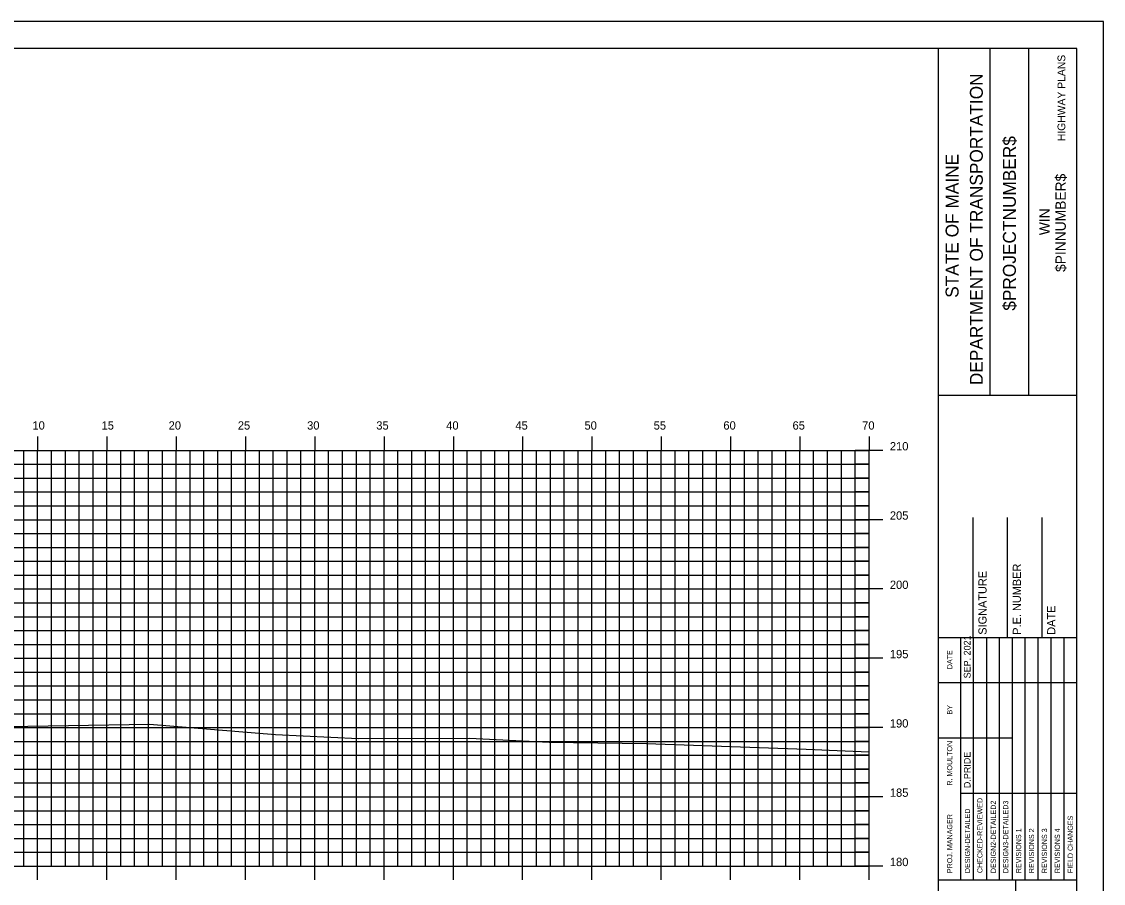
# Model space of a CAD drawing. Extents: x 1723321 to 1723493, y 458501 to 458611.
# Drawn here: x 1723412.9 to 1723490.9, y 458549 to 458611.2 of the extents above; entities that cross this region are included whole.
import ezdxf

# ---------------------------------------------------------------- set-up
doc = ezdxf.new("R2010")
doc.units = 0
for name, color, linetype in [('BORDER', 7, 'Continuous'), ('H_V ANNOTATION', 7, 'Continuous'), ('HIGHWAY_TITLE', 7, 'Continuous'), ('MAJOR', 7, 'Continuous'), ('MINOR', 7, 'Continuous'), ('PLOT BOUNDARY', 7, 'Continuous'), ('S_Roadway_Centerline', 7, 'Continuous')]:
    doc.layers.add(name, color=color, linetype=linetype)

msp = doc.modelspace()

# ---------------------------------------------------------------- linework, layer by layer
at = {"layer": 'BORDER'}
for p, q in [((1723479.029, 458504.254), (1723479.029, 458609.254)), ((1723482.758, 458584.251), (1723482.758, 458609.251)), ((1723485.553, 458584.251), (1723485.553, 458609.251)), ((1723479.03, 458584.248), (1723489.029, 458584.248)), ((1723481.529, 458566.757), (1723481.529, 458575.405)), ((1723484.029, 458566.757), (1723484.029, 458575.405)), ((1723486.529, 458566.757), (1723486.529, 458575.405)), ((1723479.029, 458566.757), (1723489.029, 458566.757)), ((1723479.029, 458549.257), (1723489.029, 458549.257)), ((1723484.62, 458514.257), (1723484.62, 458549.257))]:
    msp.add_line(p, q, dxfattribs=at)
msp.add_lwpolyline([(1723329.029, 458504.254), (1723489.029, 458504.254), (1723489.029, 458609.254), (1723329.029, 458609.254)], close=True, dxfattribs=at)
for points in [[(1723480.644, 458563.507), (1723480.644, 458566.757)], [(1723481.576, 458549.26), (1723481.576, 458566.757)], [(1723482.508, 458566.757), (1723482.508, 458549.26)], [(1723483.44, 458549.26), (1723483.44, 458566.757)], [(1723484.372, 458549.26), (1723484.372, 458566.757)], [(1723485.303, 458549.26), (1723485.303, 458566.757)], [(1723486.235, 458549.26), (1723486.235, 458566.757)], [(1723487.167, 458549.26), (1723487.167, 458566.757)], [(1723488.098, 458549.26), (1723488.098, 458566.757)], [(1723480.645, 458549.26), (1723480.645, 458566.051)], [(1723479.029, 458563.507), (1723489.029, 458563.507)], [(1723479.029, 458559.507), (1723480.645, 458559.507)], [(1723480.644, 458559.507), (1723484.371, 458559.507)], [(1723480.644, 458555.507), (1723489.029, 458555.507)]]:
    msp.add_lwpolyline(points, dxfattribs=at)
at = {"layer": 'MAJOR'}
for p, q in [((1723414.029, 458581.256), (1723414.029, 458580.254)), ((1723419.029, 458581.256), (1723419.029, 458580.254)), ((1723424.029, 458581.256), (1723424.029, 458580.254)), ((1723429.029, 458581.256), (1723429.029, 458580.254)), ((1723434.029, 458581.256), (1723434.029, 458580.254)), ((1723439.029, 458581.256), (1723439.029, 458580.254)), ((1723444.029, 458581.256), (1723444.029, 458580.254)), ((1723449.029, 458581.256), (1723449.029, 458580.254)), ((1723454.029, 458581.256), (1723454.029, 458580.254)), ((1723459.029, 458581.256), (1723459.029, 458580.254)), ((1723464.029, 458581.256), (1723464.029, 458580.254)), ((1723469.029, 458581.256), (1723469.029, 458580.254)), ((1723474.029, 458581.256), (1723474.029, 458580.254)), ((1723334.029, 458580.254), (1723474.029, 458580.254)), ((1723334.029, 458580.254), (1723474.029, 458580.254)), ((1723414.029, 458550.254), (1723414.029, 458580.254)), ((1723419.029, 458550.254), (1723419.029, 458580.254)), ((1723424.029, 458550.254), (1723424.029, 458580.254)), ((1723429.029, 458550.254), (1723429.029, 458580.254)), ((1723434.029, 458550.254), (1723434.029, 458580.254)), ((1723439.029, 458550.254), (1723439.029, 458580.254)), ((1723444.029, 458550.254), (1723444.029, 458580.254)), ((1723449.029, 458550.254), (1723449.029, 458580.254)), ((1723454.029, 458550.254), (1723454.029, 458580.254)), ((1723459.029, 458550.254), (1723459.029, 458580.254)), ((1723464.029, 458550.254), (1723464.029, 458580.254)), ((1723469.029, 458550.254), (1723469.029, 458580.254)), ((1723475.031, 458580.254), (1723473.027, 458580.254)), ((1723474.029, 458550.254), (1723474.029, 458580.254)), ((1723474.029, 458550.254), (1723474.029, 458580.254)), ((1723334.029, 458575.254), (1723474.029, 458575.254)), ((1723475.031, 458575.254), (1723473.027, 458575.254)), ((1723334.029, 458570.254), (1723474.029, 458570.254)), ((1723475.031, 458570.254), (1723473.027, 458570.254)), ((1723334.029, 458565.254), (1723474.029, 458565.254)), ((1723475.031, 458565.254), (1723473.027, 458565.254)), ((1723334.029, 458560.254), (1723474.029, 458560.254)), ((1723475.031, 458560.254), (1723473.027, 458560.254)), ((1723334.029, 458555.254), (1723474.029, 458555.254)), ((1723475.031, 458555.254), (1723473.027, 458555.254)), ((1723334.029, 458550.254), (1723474.029, 458550.254)), ((1723334.029, 458550.254), (1723474.029, 458550.254)), ((1723414.029, 458549.252), (1723414.029, 458550.254)), ((1723419.029, 458549.252), (1723419.029, 458550.254)), ((1723424.029, 458549.252), (1723424.029, 458550.254)), ((1723429.029, 458549.252), (1723429.029, 458550.254)), ((1723434.029, 458549.252), (1723434.029, 458550.254)), ((1723439.029, 458549.252), (1723439.029, 458550.254)), ((1723444.029, 458549.252), (1723444.029, 458550.254)), ((1723449.029, 458549.252), (1723449.029, 458550.254)), ((1723454.029, 458549.252), (1723454.029, 458550.254)), ((1723459.029, 458549.252), (1723459.029, 458550.254)), ((1723464.029, 458549.252), (1723464.029, 458550.254)), ((1723469.029, 458549.252), (1723469.029, 458550.254)), ((1723475.031, 458550.254), (1723473.027, 458550.254)), ((1723474.029, 458549.252), (1723474.029, 458550.254))]:
    msp.add_line(p, q, dxfattribs=at)
at = {"layer": 'MINOR'}
for p, q in [((1723413.029, 458550.254), (1723413.029, 458580.254)), ((1723415.029, 458550.254), (1723415.029, 458580.254)), ((1723416.029, 458550.254), (1723416.029, 458580.254)), ((1723417.029, 458550.254), (1723417.029, 458580.254)), ((1723418.029, 458550.254), (1723418.029, 458580.254)), ((1723420.029, 458550.254), (1723420.029, 458580.254)), ((1723421.029, 458550.254), (1723421.029, 458580.254)), ((1723422.029, 458550.254), (1723422.029, 458580.254)), ((1723423.029, 458550.254), (1723423.029, 458580.254)), ((1723425.029, 458550.254), (1723425.029, 458580.254)), ((1723426.029, 458550.254), (1723426.029, 458580.254)), ((1723427.029, 458550.254), (1723427.029, 458580.254)), ((1723428.029, 458550.254), (1723428.029, 458580.254)), ((1723430.029, 458550.254), (1723430.029, 458580.254)), ((1723431.029, 458550.254), (1723431.029, 458580.254)), ((1723432.029, 458550.254), (1723432.029, 458580.254)), ((1723433.029, 458550.254), (1723433.029, 458580.254)), ((1723435.029, 458550.254), (1723435.029, 458580.254)), ((1723436.029, 458550.254), (1723436.029, 458580.254)), ((1723437.029, 458550.254), (1723437.029, 458580.254)), ((1723438.029, 458550.254), (1723438.029, 458580.254)), ((1723440.029, 458550.254), (1723440.029, 458580.254)), ((1723441.029, 458550.254), (1723441.029, 458580.254)), ((1723442.029, 458550.254), (1723442.029, 458580.254)), ((1723443.029, 458550.254), (1723443.029, 458580.254)), ((1723445.029, 458550.254), (1723445.029, 458580.254)), ((1723446.029, 458550.254), (1723446.029, 458580.254)), ((1723447.029, 458550.254), (1723447.029, 458580.254)), ((1723448.029, 458550.254), (1723448.029, 458580.254)), ((1723450.029, 458550.254), (1723450.029, 458580.254)), ((1723451.029, 458550.254), (1723451.029, 458580.254)), ((1723452.029, 458550.254), (1723452.029, 458580.254)), ((1723453.029, 458550.254), (1723453.029, 458580.254)), ((1723455.029, 458550.254), (1723455.029, 458580.254)), ((1723456.029, 458550.254), (1723456.029, 458580.254)), ((1723457.029, 458550.254), (1723457.029, 458580.254)), ((1723458.029, 458550.254), (1723458.029, 458580.254)), ((1723460.029, 458550.254), (1723460.029, 458580.254)), ((1723461.029, 458550.254), (1723461.029, 458580.254)), ((1723462.029, 458550.254), (1723462.029, 458580.254)), ((1723463.029, 458550.254), (1723463.029, 458580.254)), ((1723465.029, 458550.254), (1723465.029, 458580.254)), ((1723466.029, 458550.254), (1723466.029, 458580.254)), ((1723467.029, 458550.254), (1723467.029, 458580.254)), ((1723468.029, 458550.254), (1723468.029, 458580.254)), ((1723470.029, 458550.254), (1723470.029, 458580.254)), ((1723471.029, 458550.254), (1723471.029, 458580.254)), ((1723472.029, 458550.254), (1723472.029, 458580.254)), ((1723473.029, 458550.254), (1723473.029, 458580.254)), ((1723334.029, 458579.254), (1723474.029, 458579.254)), ((1723474.029, 458579.254), (1723473.027, 458579.254)), ((1723334.029, 458578.254), (1723474.029, 458578.254)), ((1723474.029, 458578.254), (1723473.027, 458578.254)), ((1723334.029, 458577.254), (1723474.029, 458577.254)), ((1723474.029, 458577.254), (1723473.027, 458577.254)), ((1723334.029, 458576.254), (1723474.029, 458576.254)), ((1723474.029, 458576.254), (1723473.027, 458576.254)), ((1723334.029, 458574.254), (1723474.029, 458574.254)), ((1723474.029, 458574.254), (1723473.027, 458574.254)), ((1723334.029, 458573.254), (1723474.029, 458573.254)), ((1723474.029, 458573.254), (1723473.027, 458573.254)), ((1723334.029, 458572.254), (1723474.029, 458572.254)), ((1723474.029, 458572.254), (1723473.027, 458572.254)), ((1723334.029, 458571.254), (1723474.029, 458571.254)), ((1723474.029, 458571.254), (1723473.027, 458571.254)), ((1723334.029, 458569.254), (1723474.029, 458569.254)), ((1723474.029, 458569.254), (1723473.027, 458569.254)), ((1723334.029, 458568.254), (1723474.029, 458568.254)), ((1723474.029, 458568.254), (1723473.027, 458568.254)), ((1723334.029, 458567.254), (1723474.029, 458567.254)), ((1723474.029, 458567.254), (1723473.027, 458567.254)), ((1723334.029, 458566.254), (1723474.029, 458566.254)), ((1723474.029, 458566.254), (1723473.027, 458566.254)), ((1723334.029, 458564.254), (1723474.029, 458564.254)), ((1723474.029, 458564.254), (1723473.027, 458564.254)), ((1723334.029, 458563.254), (1723474.029, 458563.254)), ((1723474.029, 458563.254), (1723473.027, 458563.254)), ((1723334.029, 458562.254), (1723474.029, 458562.254)), ((1723474.029, 458562.254), (1723473.027, 458562.254)), ((1723334.029, 458561.254), (1723474.029, 458561.254)), ((1723474.029, 458561.254), (1723473.027, 458561.254)), ((1723334.029, 458559.254), (1723474.029, 458559.254)), ((1723474.029, 458559.254), (1723473.027, 458559.254)), ((1723334.029, 458558.254), (1723474.029, 458558.254)), ((1723474.029, 458558.254), (1723473.027, 458558.254)), ((1723334.029, 458557.254), (1723474.029, 458557.254)), ((1723474.029, 458557.254), (1723473.027, 458557.254)), ((1723334.029, 458556.254), (1723474.029, 458556.254)), ((1723474.029, 458556.254), (1723473.027, 458556.254)), ((1723334.029, 458554.254), (1723474.029, 458554.254)), ((1723474.029, 458554.254), (1723473.027, 458554.254)), ((1723334.029, 458553.254), (1723474.029, 458553.254)), ((1723474.029, 458553.254), (1723473.027, 458553.254)), ((1723334.029, 458552.254), (1723474.029, 458552.254)), ((1723474.029, 458552.254), (1723473.027, 458552.254)), ((1723334.029, 458551.254), (1723474.029, 458551.254)), ((1723474.029, 458551.254), (1723473.027, 458551.254))]:
    msp.add_line(p, q, dxfattribs=at)
at = {"layer": 'PLOT BOUNDARY'}
msp.add_lwpolyline([(1723320.936, 458501.195), (1723490.936, 458501.195), (1723490.936, 458611.195), (1723320.936, 458611.195)], close=True, dxfattribs=at)
at = {"layer": 'S_Roadway_Centerline'}
msp.add_lwpolyline([(1723334.029, 458562.416), (1723335.834, 458562.354), (1723338.025, 458562.255), (1723349.598, 458561.79), (1723356.493, 458561.701), (1723361.621, 458561.642), (1723371.34, 458561.107), (1723375.346, 458560.975), (1723380.963, 458560.978), (1723398.602, 458560.98), (1723404.466, 458560.596), (1723411.856, 458560.327), (1723422.097, 458560.488), (1723431.206, 458559.748), (1723437.19, 458559.453), (1723445.206, 458559.48), (1723450.944, 458559.196), (1723457.969, 458559.095), (1723469.498, 458558.688), (1723470.086, 458558.662), (1723471.145, 458558.626), (1723474.029, 458558.512)], dxfattribs=at)

# ---------------------------------------------------------------- texts
at = {"layer": 'BORDER'}
for s, height, p in [('DEPARTMENT OF TRANSPORTATION', 0.93176, (1723482.236, 458584.96)), ('$PROJECTNUMBER$', 0.93176, (1723484.621, 458590.333)), ('STATE OF MAINE', 0.93176, (1723480.484, 458591.266)), ('$PINNUMBER$', 0.74527, (1723488.225, 458593.129)), ('WIN', 0.7453, (1723487.066, 458595.784)), ('P.E. NUMBER', 0.59055, (1723484.99, 458566.949)), ('SIGNATURE', 0.5906, (1723482.509, 458566.949)), ('DATE', 0.5906, (1723487.47, 458566.949)), ('SEP. 2021', 0.4845, (1723481.352, 458563.803)), ('DATE', 0.3714, (1723480.033, 458564.463)), ('BY', 0.3714, (1723480.033, 458561.192)), ('R. MOULTON', 0.3727, (1723480.033, 458556.06)), ('D.PRIDE', 0.4845, (1723481.352, 458555.88)), ('CHECKED-REVIEWED', 0.37275, (1723482.21, 458549.745)), ('DESIGN2-DETAILED2', 0.37275, (1723483.179, 458549.745)), ('DESIGN3-DETAILED3', 0.37275, (1723484.073, 458549.745)), ('DESIGN-DETAILED', 0.37275, (1723481.316, 458549.745)), ('PROJ. MANAGER', 0.37275, (1723480.033, 458549.745)), ('FIELD CHANGES', 0.37275, (1723488.732, 458549.745)), ('REVISIONS 1', 0.37275, (1723485.005, 458549.745)), ('REVISIONS 2', 0.37275, (1723485.937, 458549.745)), ('REVISIONS 3', 0.37275, (1723486.868, 458549.745)), ('REVISIONS 4', 0.37275, (1723487.8, 458549.745))]:
    msp.add_text(s, height=height, rotation=90, dxfattribs=at).set_placement(p)
at = {"layer": 'H_V ANNOTATION'}
for s, p in [('10', (1723413.654, 458581.754)), ('15', (1723418.646, 458581.754)), ('20', (1723423.483, 458581.754)), ('25', (1723428.475, 458581.754)), ('30', (1723433.477, 458581.754)), ('35', (1723438.469, 458581.754)), ('40', (1723443.515, 458581.754)), ('45', (1723448.507, 458581.754)), ('50', (1723453.493, 458581.754)), ('55', (1723458.485, 458581.754)), ('60', (1723463.515, 458581.754)), ('65', (1723468.507, 458581.754)), ('70', (1723473.531, 458581.754)), ('210', (1723475.529, 458580.254)), ('205', (1723475.529, 458575.254)), ('200', (1723475.529, 458570.254)), ('195', (1723475.529, 458565.254)), ('190', (1723475.529, 458560.254)), ('185', (1723475.529, 458555.254)), ('180', (1723475.529, 458550.254))]:
    msp.add_text(s, height=0.6, dxfattribs=at).set_placement(p)
at = {"layer": 'HIGHWAY_TITLE'}
msp.add_text('HIGHWAY PLANS', height=0.55901, rotation=90, dxfattribs=at).set_placement((1723488.187, 458602.57))

doc.saveas('drawing.dxf')
